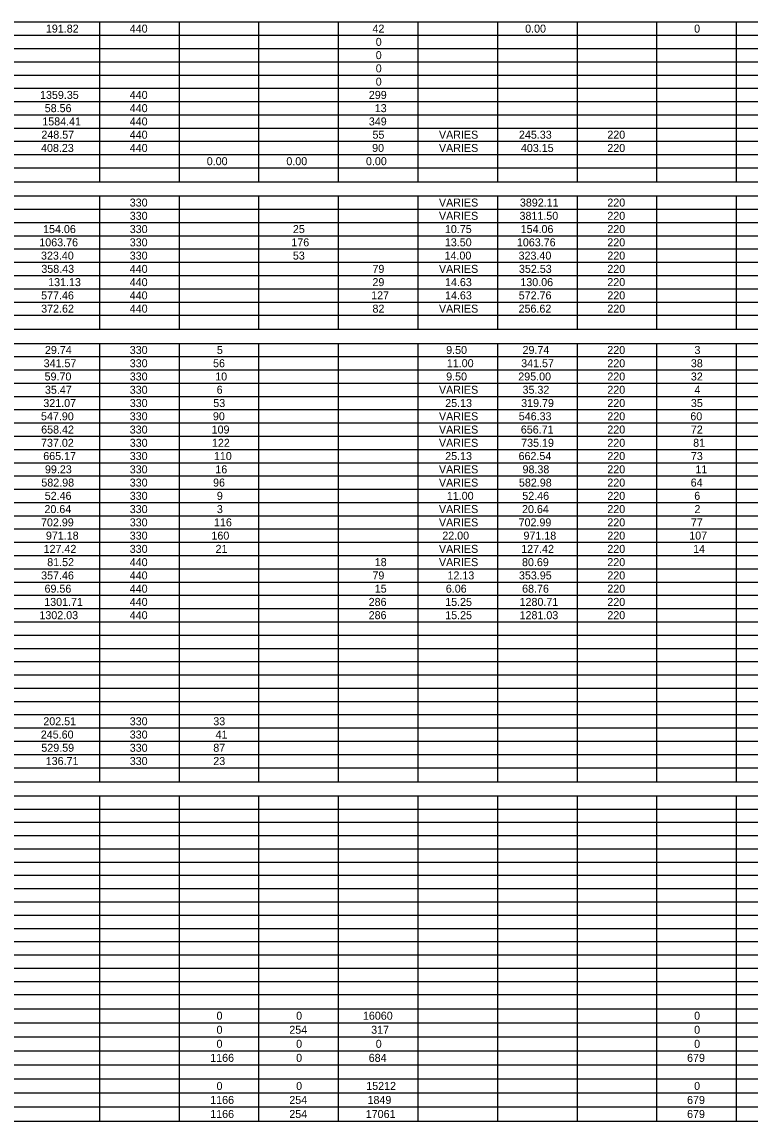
# Model space of a CAD drawing. Extents: x 1226590 to 1228573, y 151304 to 154224.
# Drawn here: x 1227629 to 1228084, y 152628 to 153315 of the extents above; entities that cross this region are included whole.
import ezdxf

# ---------------------------------------------------------------- set-up
doc = ezdxf.new("R2010")
doc.units = 0
doc.layers.add('R_Dimension', color=7, linetype='Continuous')

msp = doc.modelspace()

# ---------------------------------------------------------------- linework, layer by layer
at = {"layer": 'R_Dimension'}
for p, q in [((1226590.27, 153314.5), (1228572.93, 153314.5)), ((1227677.88, 153214.57), (1227677.88, 153314.5)), ((1227727.61, 153214.57), (1227727.61, 153314.5)), ((1227777.33, 153214.57), (1227777.33, 153314.5)), ((1227827.06, 153214.57), (1227827.06, 153314.5)), ((1227876.78, 153214.57), (1227876.78, 153314.5)), ((1227926.51, 153214.57), (1227926.51, 153314.5)), ((1227976.23, 153214.57), (1227976.23, 153314.5)), ((1228025.96, 153214.57), (1228025.96, 153314.5)), ((1228075.68, 153214.57), (1228075.68, 153314.5)), ((1226590.27, 153306.22), (1228572.93, 153306.22)), ((1226590.27, 153297.93), (1228572.93, 153297.93)), ((1226590.27, 153289.64), (1228572.93, 153289.64)), ((1226590.27, 153281.35), (1228572.93, 153281.35)), ((1226590.27, 153273.07), (1228572.93, 153273.07)), ((1226590.27, 153264.78), (1228572.93, 153264.78)), ((1226590.27, 153256.49), (1228572.93, 153256.49)), ((1226590.27, 153248.2), (1228572.93, 153248.2)), ((1226590.27, 153239.92), (1228572.93, 153239.92)), ((1226590.27, 153231.63), (1228572.93, 153231.63)), ((1226590.27, 153223.34), (1228572.93, 153223.34)), ((1226590.27, 153214.57), (1228572.93, 153214.57)), ((1226590.27, 153205.79), (1228572.93, 153205.79)), ((1227677.88, 153122.43), (1227677.88, 153205.79)), ((1227727.61, 153122.43), (1227727.61, 153205.79)), ((1227777.33, 153122.43), (1227777.33, 153205.79)), ((1227827.06, 153122.43), (1227827.06, 153205.79)), ((1227876.78, 153122.43), (1227876.78, 153205.79)), ((1227926.51, 153122.43), (1227926.51, 153205.79)), ((1227976.23, 153122.43), (1227976.23, 153205.79)), ((1228025.96, 153122.43), (1228025.96, 153205.79)), ((1228075.68, 153122.43), (1228075.68, 153205.79)), ((1226590.27, 153197.5), (1228572.93, 153197.5)), ((1226590.27, 153189.22), (1228572.93, 153189.22)), ((1226590.27, 153180.93), (1228572.93, 153180.93)), ((1226590.27, 153172.64), (1228572.93, 153172.64)), ((1226590.27, 153164.35), (1228572.93, 153164.35)), ((1226590.27, 153156.07), (1228572.93, 153156.07)), ((1226590.27, 153147.78), (1228572.93, 153147.78)), ((1226590.27, 153139.49), (1228572.93, 153139.49)), ((1226590.27, 153131.2), (1228572.93, 153131.2)), ((1226590.27, 153122.43), (1228572.93, 153122.43)), ((1226590.27, 153113.65), (1228572.93, 153113.65)), ((1227677.88, 152839.68), (1227677.88, 153113.65)), ((1227727.61, 152839.68), (1227727.61, 153113.65)), ((1227777.33, 152839.68), (1227777.33, 153113.65)), ((1227827.06, 152839.68), (1227827.06, 153113.65)), ((1227876.78, 152839.68), (1227876.78, 153113.65)), ((1227926.51, 152839.68), (1227926.51, 153113.65)), ((1227976.23, 152839.68), (1227976.23, 153113.65)), ((1228025.96, 152839.68), (1228025.96, 153113.65)), ((1228075.68, 152839.68), (1228075.68, 153113.65)), ((1226590.27, 153105.37), (1228572.93, 153105.37)), ((1226590.27, 153097.08), (1228572.93, 153097.08)), ((1226590.27, 153088.79), (1228572.93, 153088.79)), ((1226590.27, 153080.5), (1228572.93, 153080.5)), ((1226590.27, 153072.22), (1228572.93, 153072.22)), ((1226590.27, 153063.93), (1228572.93, 153063.93)), ((1226590.27, 153055.64), (1228572.93, 153055.64)), ((1226590.27, 153047.35), (1228572.93, 153047.35)), ((1226590.27, 153039.07), (1228572.93, 153039.07)), ((1226590.27, 153030.78), (1228572.93, 153030.78)), ((1226590.27, 153022.49), (1228572.93, 153022.49)), ((1226590.27, 153014.2), (1228572.93, 153014.2)), ((1226590.27, 153005.92), (1228572.93, 153005.92)), ((1226590.27, 152997.63), (1228572.93, 152997.63)), ((1226590.27, 152989.34), (1228572.93, 152989.34)), ((1226590.27, 152981.05), (1228572.93, 152981.05)), ((1226590.27, 152972.77), (1228572.93, 152972.77)), ((1226590.27, 152964.48), (1228572.93, 152964.48)), ((1226590.27, 152956.19), (1228572.93, 152956.19)), ((1226590.27, 152947.9), (1228572.93, 152947.9)), ((1226590.27, 152939.62), (1228572.93, 152939.62)), ((1226590.27, 152931.33), (1228572.93, 152931.33)), ((1226590.27, 152923.04), (1228572.93, 152923.04)), ((1226590.27, 152914.75), (1228572.93, 152914.75)), ((1226590.27, 152906.47), (1228572.93, 152906.47)), ((1226590.27, 152898.18), (1228572.93, 152898.18)), ((1226590.27, 152889.89), (1228572.93, 152889.89)), ((1226590.27, 152881.6), (1228572.93, 152881.6)), ((1226590.27, 152873.32), (1228572.93, 152873.32)), ((1226590.27, 152865.03), (1228572.93, 152865.03)), ((1226590.27, 152856.74), (1228572.93, 152856.74)), ((1226590.27, 152848.45), (1228572.93, 152848.45)), ((1226590.27, 152839.68), (1228572.93, 152839.68)), ((1226590.27, 152830.9), (1228572.93, 152830.9)), ((1227677.88, 152627.62), (1227677.88, 152830.9)), ((1227727.61, 152627.62), (1227727.61, 152830.9)), ((1227777.33, 152627.62), (1227777.33, 152830.9)), ((1227827.06, 152627.62), (1227827.06, 152830.9)), ((1227876.78, 152627.62), (1227876.78, 152830.9)), ((1227926.51, 152627.62), (1227926.51, 152830.9)), ((1227976.23, 152627.62), (1227976.23, 152830.9)), ((1228025.96, 152627.62), (1228025.96, 152830.9)), ((1228075.68, 152627.62), (1228075.68, 152830.9)), ((1226590.27, 152822.62), (1228572.93, 152822.62)), ((1226590.27, 152814.33), (1228572.93, 152814.33)), ((1226590.27, 152806.04), (1228572.93, 152806.04)), ((1226590.27, 152797.75), (1228572.93, 152797.75)), ((1226590.27, 152789.47), (1228572.93, 152789.47)), ((1226590.27, 152781.18), (1228572.93, 152781.18)), ((1226590.27, 152772.89), (1228572.93, 152772.89)), ((1226590.27, 152764.6), (1228572.93, 152764.6)), ((1226590.27, 152756.32), (1228572.93, 152756.32)), ((1226590.27, 152748.03), (1228572.93, 152748.03)), ((1226590.27, 152739.74), (1228572.93, 152739.74)), ((1226590.27, 152731.45), (1228572.93, 152731.45)), ((1226590.27, 152723.17), (1228572.93, 152723.17)), ((1226590.27, 152714.88), (1228572.93, 152714.88)), ((1226590.27, 152706.59), (1228572.93, 152706.59)), ((1226590.27, 152697.82), (1228572.93, 152697.82)), ((1226590.27, 152689.04), (1228572.93, 152689.04)), ((1226590.27, 152680.27), (1228572.93, 152680.27)), ((1226590.27, 152671.49), (1228572.93, 152671.49)), ((1226590.27, 152662.72), (1228572.93, 152662.72)), ((1226590.27, 152653.94), (1228572.93, 152653.94)), ((1226590.27, 152645.17), (1228572.93, 152645.17)), ((1226590.27, 152636.39), (1228572.93, 152636.39)), ((1226590.27, 152627.62), (1228572.93, 152627.62))]:
    msp.add_line(p, q, dxfattribs=at)

# ---------------------------------------------------------------- texts
for s, p in [('191.82', (1227644.24, 153307.86)), ('440', (1227696.62, 153307.86)), ('42', (1227848.26, 153307.86)), ('0.00', (1227943.63, 153307.86)), ('0', (1228049.19, 153307.86)), ('0', (1227850.29, 153299.57)), ('0', (1227850.29, 153291.29)), ('0', (1227850.29, 153283)), ('0', (1227850.29, 153274.71)), ('1359.35', (1227640.58, 153266.42)), ('440', (1227696.62, 153266.42)), ('299', (1227845.99, 153266.42)), ('58.56', (1227643.51, 153258.14)), ('440', (1227696.62, 153258.14)), ('13', (1227849.68, 153258.14)), ('1584.41', (1227642, 153249.85)), ('440', (1227696.62, 153249.85)), ('349', (1227845.99, 153249.85)), ('248.57', (1227641.41, 153241.56)), ('440', (1227696.62, 153241.56)), ('55', (1227848.26, 153241.56)), ('VARIES', (1227889.79, 153241.56)), ('245.33', (1227939.76, 153241.56)), ('220', (1227994.97, 153241.56)), ('408.23', (1227641.21, 153233.27)), ('440', (1227696.62, 153233.27)), ('90', (1227848.04, 153233.27)), ('VARIES', (1227889.79, 153233.27)), ('403.15', (1227940.98, 153233.27)), ('220', (1227994.97, 153233.27)), ('0.00', (1227744.73, 153224.99)), ('0.00', (1227794.46, 153224.99)), ('0.00', (1227844.18, 153224.99)), ('330', (1227696.62, 153199.15)), ('VARIES', (1227889.79, 153199.15)), ('3892.11', (1227940.35, 153199.15)), ('220', (1227994.97, 153199.15)), ('330', (1227696.62, 153190.86)), ('VARIES', (1227889.79, 153190.86)), ('3811.50', (1227940.13, 153190.86)), ('220', (1227994.97, 153190.86)), ('154.06', (1227642.49, 153182.57)), ('330', (1227696.62, 153182.57)), ('25', (1227798.53, 153182.57)), ('10.75', (1227893.5, 153182.57)), ('154.06', (1227940.84, 153182.57)), ('220', (1227994.97, 153182.57)), ('1063.76', (1227640.13, 153174.29)), ('330', (1227696.62, 153174.29)), ('176', (1227797.57, 153174.29)), ('13.50', (1227893.48, 153174.29)), ('1063.76', (1227938.48, 153174.29)), ('220', (1227994.97, 153174.29)), ('323.40', (1227641.19, 153166)), ('330', (1227696.62, 153166)), ('53', (1227798.53, 153166)), ('14.00', (1227893.28, 153166)), ('323.40', (1227939.54, 153166)), ('220', (1227994.97, 153166)), ('358.43', (1227641.41, 153157.71)), ('440', (1227696.62, 153157.71)), ('79', (1227848.24, 153157.71)), ('VARIES', (1227889.79, 153157.71)), ('352.53', (1227939.76, 153157.71)), ('220', (1227994.97, 153157.71)), ('131.13', (1227645.66, 153149.42)), ('440', (1227696.62, 153149.42)), ('29', (1227848.24, 153149.42)), ('14.63', (1227893.57, 153149.42)), ('130.06', (1227940.64, 153149.42)), ('220', (1227994.97, 153149.42)), ('577.46', (1227641.27, 153141.14)), ('440', (1227696.62, 153141.14)), ('127', (1227847.43, 153141.14)), ('14.63', (1227893.57, 153141.14)), ('572.76', (1227939.62, 153141.14)), ('220', (1227994.97, 153141.14)), ('372.62', (1227641.29, 153132.85)), ('440', (1227696.62, 153132.85)), ('82', (1227848.26, 153132.85)), ('VARIES', (1227889.79, 153132.85)), ('256.62', (1227939.52, 153132.85)), ('220', (1227994.97, 153132.85)), ('29.74', (1227643.65, 153107.01)), ('330', (1227696.62, 153107.01)), ('5', (1227751.05, 153107.01)), ('9.50', (1227894.3, 153107.01)), ('29.74', (1227942, 153107.01)), ('220', (1227994.97, 153107.01)), ('3', (1228049.4, 153107.01)), ('341.57', (1227642.82, 153098.72)), ('330', (1227696.62, 153098.72)), ('56', (1227748.67, 153098.72)), ('11.00', (1227894.7, 153098.72)), ('341.57', (1227941.17, 153098.72)), ('220', (1227994.97, 153098.72)), ('38', (1228047.16, 153098.72)), ('59.70', (1227643.43, 153090.44)), ('330', (1227696.62, 153090.44)), ('10', (1227750.01, 153090.44)), ('9.50', (1227894.3, 153090.44)), ('295.00', (1227939.34, 153090.44)), ('220', (1227994.97, 153090.44)), ('32', (1228047.16, 153090.44)), ('35.47', (1227643.65, 153082.15)), ('330', (1227696.62, 153082.15)), ('6', (1227750.92, 153082.15)), ('VARIES', (1227889.79, 153082.15)), ('35.32', (1227942, 153082.15)), ('220', (1227994.97, 153082.15)), ('4', (1228049.4, 153082.15)), ('321.07', (1227642.63, 153073.86)), ('330', (1227696.62, 153073.86)), ('53', (1227748.81, 153073.86)), ('25.13', (1227893.69, 153073.86)), ('319.79', (1227941.15, 153073.86)), ('220', (1227994.97, 153073.86)), ('35', (1228047.16, 153073.86)), ('547.90', (1227641.19, 153065.57)), ('330', (1227696.62, 153065.57)), ('90', (1227748.59, 153065.57)), ('VARIES', (1227889.79, 153065.57)), ('546.33', (1227939.64, 153065.57)), ('220', (1227994.97, 153065.57)), ('60', (1228046.82, 153065.57)), ('658.42', (1227641.29, 153057.29)), ('330', (1227696.62, 153057.29)), ('109', (1227747.77, 153057.29)), ('VARIES', (1227889.79, 153057.29)), ('656.71', (1227940.94, 153057.29)), ('220', (1227994.97, 153057.29)), ('72', (1228047.16, 153057.29)), ('737.02', (1227641.21, 153049)), ('330', (1227696.62, 153049)), ('122', (1227747.98, 153049)), ('VARIES', (1227889.79, 153049)), ('735.19', (1227941.15, 153049)), ('220', (1227994.97, 153049)), ('81', (1228048.58, 153049)), ('665.17', (1227642.59, 153040.71)), ('330', (1227696.62, 153040.71)), ('110', (1227749.18, 153040.71)), ('25.13', (1227893.69, 153040.71)), ('662.54', (1227939.52, 153040.71)), ('220', (1227994.97, 153040.71)), ('73', (1228047.16, 153040.71)), ('99.23', (1227643.65, 153032.42)), ('330', (1227696.62, 153032.42)), ('16', (1227750.09, 153032.42)), ('VARIES', (1227889.79, 153032.42)), ('98.38', (1227942, 153032.42)), ('220', (1227994.97, 153032.42)), ('11', (1228049.99, 153032.42)), ('582.98', (1227641.41, 153024.14)), ('330', (1227696.62, 153024.14)), ('96', (1227748.67, 153024.14)), ('VARIES', (1227889.79, 153024.14)), ('582.98', (1227939.76, 153024.14)), ('220', (1227994.97, 153024.14)), ('64', (1228047.04, 153024.14)), ('52.46', (1227643.51, 153015.85)), ('330', (1227696.62, 153015.85)), ('9', (1227751.03, 153015.85)), ('11.00', (1227894.7, 153015.85)), ('52.46', (1227941.86, 153015.85)), ('220', (1227994.97, 153015.85)), ('6', (1228049.27, 153015.85)), ('20.64', (1227643.34, 153007.56)), ('330', (1227696.62, 153007.56)), ('3', (1227751.05, 153007.56)), ('VARIES', (1227889.79, 153007.56)), ('20.64', (1227941.69, 153007.56)), ('220', (1227994.97, 153007.56)), ('2', (1228049.4, 153007.56)), ('702.99', (1227641.19, 152999.27)), ('330', (1227696.62, 152999.27)), ('116', (1227749.26, 152999.27)), ('VARIES', (1227889.79, 152999.27)), ('702.99', (1227939.54, 152999.27)), ('220', (1227994.97, 152999.27)), ('77', (1228047.16, 152999.27)), ('971.18', (1227644.24, 152990.99)), ('330', (1227696.62, 152990.99)), ('160', (1227747.65, 152990.99)), ('22.00', (1227891.86, 152990.99)), ('971.18', (1227942.59, 152990.99)), ('220', (1227994.97, 152990.99)), ('107', (1228046.14, 152990.99)), ('127.42', (1227642.82, 152982.7)), ('330', (1227696.62, 152982.7)), ('21', (1227750.23, 152982.7)), ('VARIES', (1227889.79, 152982.7)), ('127.42', (1227941.17, 152982.7)), ('220', (1227994.97, 152982.7)), ('14', (1228048.58, 152982.7)), ('81.52', (1227645.07, 152974.41)), ('440', (1227696.62, 152974.41)), ('18', (1227849.68, 152974.41)), ('VARIES', (1227889.79, 152974.41)), ('80.69', (1227941.67, 152974.41)), ('220', (1227994.97, 152974.41)), ('357.46', (1227641.27, 152966.12)), ('440', (1227696.62, 152966.12)), ('79', (1227848.24, 152966.12)), ('12.13', (1227895.11, 152966.12)), ('353.95', (1227939.76, 152966.12)), ('220', (1227994.97, 152966.12)), ('69.56', (1227643.39, 152957.84)), ('440', (1227696.62, 152957.84)), ('15', (1227849.68, 152957.84)), ('6.06', (1227894.07, 152957.84)), ('68.76', (1227941.74, 152957.84)), ('220', (1227994.97, 152957.84)), ('1301.71', (1227643.22, 152949.55)), ('440', (1227696.62, 152949.55)), ('286', (1227845.88, 152949.55)), ('15.25', (1227893.69, 152949.55)), ('1280.71', (1227940.15, 152949.55)), ('220', (1227994.97, 152949.55)), ('1302.03', (1227640.19, 152941.26)), ('440', (1227696.62, 152941.26)), ('286', (1227845.88, 152941.26)), ('15.25', (1227893.69, 152941.26)), ('1281.03', (1227940.15, 152941.26)), ('220', (1227994.97, 152941.26)), ('202.51', (1227642.63, 152874.96)), ('330', (1227696.62, 152874.96)), ('33', (1227748.81, 152874.96)), ('245.60', (1227641.07, 152866.67)), ('330', (1227696.62, 152866.67)), ('41', (1227750.23, 152866.67)), ('529.59', (1227641.39, 152858.39)), ('330', (1227696.62, 152858.39)), ('87', (1227748.81, 152858.39)), ('136.71', (1227644.12, 152850.1)), ('330', (1227696.62, 152850.1)), ('23', (1227748.81, 152850.1)), ('0', (1227750.84, 152690.93)), ('0', (1227800.56, 152690.93)), ('16060', (1227842.29, 152690.93)), ('0', (1228049.19, 152690.93)), ('0', (1227750.84, 152682.15)), ('254', (1227796.29, 152682.15)), ('317', (1227847.43, 152682.15)), ('0', (1228049.19, 152682.15)), ('0', (1227750.84, 152673.38)), ('0', (1227800.56, 152673.38)), ('0', (1227850.29, 152673.38)), ('0', (1228049.19, 152673.38)), ('1166', (1227746.9, 152664.6)), ('0', (1227800.56, 152664.6)), ('684', (1227845.9, 152664.6)), ('679', (1228044.78, 152664.6)), ('0', (1227750.84, 152647.05)), ('0', (1227800.56, 152647.05)), ('15212', (1227844.36, 152647.05)), ('0', (1228049.19, 152647.05)), ('1166', (1227746.9, 152638.28)), ('254', (1227796.29, 152638.28)), ('1849', (1227845.17, 152638.28)), ('679', (1228044.78, 152638.28)), ('1166', (1227746.9, 152629.5)), ('254', (1227796.29, 152629.5)), ('17061', (1227844.05, 152629.5)), ('679', (1228044.78, 152629.5))]:
    msp.add_text(s, height=5, dxfattribs=at).set_placement(p)

doc.saveas('drawing.dxf')
